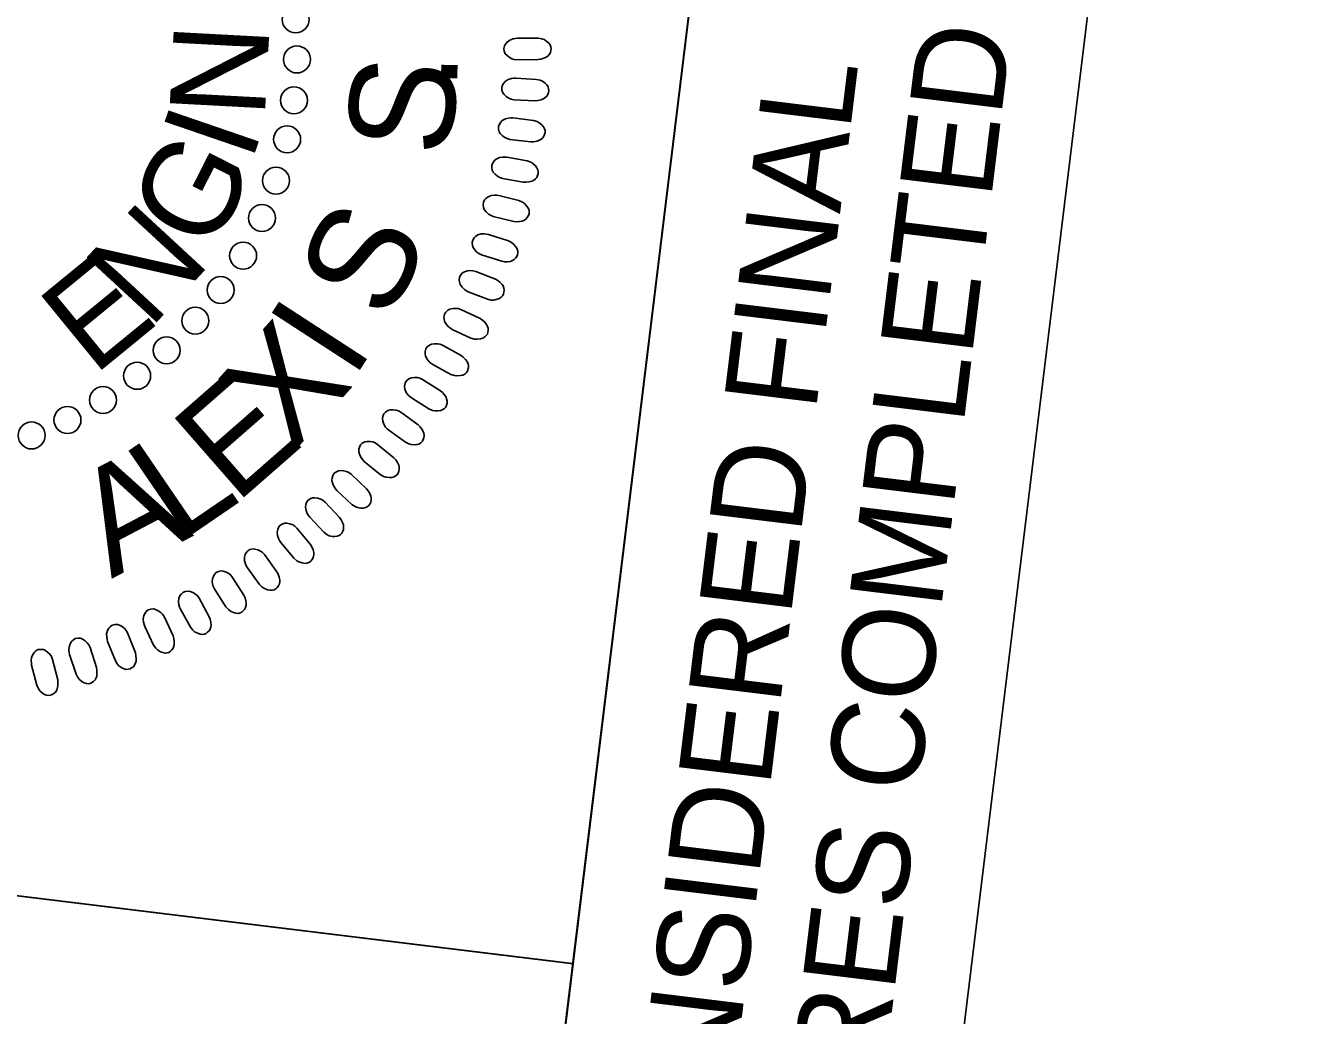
# Model space of a CAD drawing. Extents: x 480792 to 482083, y 490046 to 491850.
# Drawn here: x 481120.5 to 481196.3, y 491710 to 491768.8 of the extents above; entities that cross this region are included whole.
import ezdxf

# ---------------------------------------------------------------- set-up
doc = ezdxf.new("R2010")
doc.units = 0
for name, color, linetype in [('Sheet PE Seal Cell', 7, 'Continuous'), ('Sheet Plan CELL', 7, 'Continuous'), ('Sheet Sticker Exception Certification CELL', 7, 'Continuous')]:
    doc.layers.add(name, color=color, linetype=linetype)

msp = doc.modelspace()

# ---------------------------------------------------------------- linework, layer by layer
at = {"layer": 'Sheet PE Seal Cell'}
for points in [[(481149.711, 491768.037), (481150.937, 491768.041), (481151.157, 491768.005), (481151.297, 491767.954), (481151.467, 491767.842), (481151.577, 491767.745), (481151.657, 491767.633), (481151.697, 491767.529), (481151.718, 491767.416), (481151.698, 491767.305), (481151.669, 491767.185), (481151.61, 491767.08), (481151.51, 491766.975), (481151.43, 491766.915), (481151.281, 491766.847), (481151.102, 491766.786), (481150.942, 491766.763), (481149.686, 491766.751), (481149.516, 491766.773), (481149.376, 491766.818), (481149.217, 491766.907), (481149.077, 491767.017), (481148.996, 491767.115), (481148.936, 491767.271), (481148.915, 491767.422), (481148.955, 491767.571), (481149.005, 491767.676), (481149.103, 491767.803), (481149.272, 491767.923), (481149.452, 491767.991), (481149.581, 491768.021)], [(481149.616, 491765.665), (481150.841, 491765.592), (481151.058, 491765.543), (481151.194, 491765.483), (481151.357, 491765.36), (481151.461, 491765.257), (481151.533, 491765.14), (481151.567, 491765.034), (481151.58, 491764.92), (481151.553, 491764.81), (481151.517, 491764.692), (481151.451, 491764.591), (481151.345, 491764.492), (481151.262, 491764.437), (481151.109, 491764.379), (481150.926, 491764.33), (481150.765, 491764.317), (481149.51, 491764.383), (481149.342, 491764.416), (481149.206, 491764.469), (481149.052, 491764.569), (481148.919, 491764.688), (481148.845, 491764.79), (481148.795, 491764.95), (481148.784, 491765.101), (481148.832, 491765.247), (481148.888, 491765.349), (481148.995, 491765.47), (481149.172, 491765.579), (481149.355, 491765.636), (481149.486, 491765.658)], [(481149.451, 491763.301), (481150.669, 491763.151), (481150.881, 491763.088), (481151.014, 491763.019), (481151.169, 491762.887), (481151.266, 491762.777), (481151.331, 491762.656), (481151.358, 491762.548), (481151.364, 491762.434), (481151.331, 491762.325), (481151.287, 491762.21), (481151.215, 491762.113), (481151.103, 491762.021), (481151.016, 491761.972), (481150.859, 491761.923), (481150.674, 491761.886), (481150.513, 491761.883), (481149.265, 491762.028), (481149.1, 491762.071), (481148.966, 491762.133), (481148.819, 491762.241), (481148.694, 491762.369), (481148.626, 491762.476), (481148.586, 491762.639), (481148.585, 491762.79), (481148.642, 491762.933), (481148.705, 491763.031), (481148.818, 491763.145), (481149.001, 491763.243), (481149.188, 491763.288), (481149.32, 491763.301)], [(481149.094, 491760.974), (481150.3, 491760.748), (481150.509, 491760.671), (481150.637, 491760.594), (481150.783, 491760.453), (481150.873, 491760.337), (481150.93, 491760.213), (481150.951, 491760.102), (481150.949, 491759.988), (481150.909, 491759.882), (481150.858, 491759.77), (481150.78, 491759.678), (481150.663, 491759.594), (481150.573, 491759.549), (481150.414, 491759.51), (481150.226, 491759.484), (481150.065, 491759.492), (481148.829, 491759.715), (481148.666, 491759.768), (481148.537, 491759.838), (481148.397, 491759.956), (481148.28, 491760.091), (481148.22, 491760.202), (481148.19, 491760.367), (481148.198, 491760.518), (481148.265, 491760.658), (481148.333, 491760.751), (481148.454, 491760.858), (481148.643, 491760.944), (481148.832, 491760.977), (481148.964, 491760.982)], [(481148.617, 491758.697), (481149.807, 491758.397), (481150.01, 491758.307), (481150.133, 491758.222), (481150.27, 491758.072), (481150.352, 491757.95), (481150.403, 491757.822), (481150.415, 491757.711), (481150.407, 491757.597), (481150.36, 491757.494), (481150.302, 491757.385), (481150.219, 491757.298), (481150.096, 491757.222), (481150.004, 491757.183), (481149.842, 491757.154), (481149.654, 491757.14), (481149.494, 491757.157), (481148.274, 491757.458), (481148.115, 491757.521), (481147.99, 491757.6), (481147.858, 491757.725), (481147.749, 491757.868), (481147.696, 491757.982), (481147.676, 491758.149), (481147.694, 491758.299), (481147.769, 491758.434), (481147.843, 491758.523), (481147.971, 491758.622), (481148.164, 491758.695), (481148.355, 491758.717), (481148.488, 491758.714)], [(481148.007, 491756.388), (481149.175, 491756.013), (481149.372, 491755.911), (481149.49, 491755.819), (481149.617, 491755.66), (481149.691, 491755.534), (481149.733, 491755.403), (481149.739, 491755.291), (481149.723, 491755.178), (481149.671, 491755.078), (481149.606, 491754.973), (481149.517, 491754.891), (481149.39, 491754.822), (481149.296, 491754.789), (481149.133, 491754.771), (481148.943, 491754.769), (481148.784, 491754.796), (481147.586, 491755.173), (481147.431, 491755.246), (481147.312, 491755.332), (481147.187, 491755.466), (481147.089, 491755.615), (481147.042, 491755.732), (481147.033, 491755.899), (481147.06, 491756.049), (481147.144, 491756.178), (481147.223, 491756.263), (481147.356, 491756.354), (481147.554, 491756.415), (481147.746, 491756.425), (481147.878, 491756.413)], [(481146.798, 491752.988), (481147.94, 491752.54), (481148.157, 491752.496), (481148.307, 491752.493), (481148.506, 491752.536), (481148.644, 491752.586), (481148.758, 491752.662), (481148.834, 491752.744), (481148.893, 491752.841), (481148.915, 491752.953), (481148.931, 491753.076), (481148.914, 491753.194), (481148.859, 491753.328), (481148.807, 491753.413), (481148.692, 491753.53), (481148.546, 491753.651), (481148.406, 491753.73), (481147.239, 491754.196), (481147.073, 491754.236), (481146.926, 491754.245), (481146.745, 491754.22), (481146.574, 491754.167), (481146.464, 491754.105), (481146.351, 491753.981), (481146.279, 491753.849), (481146.261, 491753.695), (481146.27, 491753.58), (481146.316, 491753.425), (481146.43, 491753.252), (481146.573, 491753.123), (481146.683, 491753.049)], [(481145.847, 491750.754), (481146.959, 491750.236), (481147.174, 491750.177), (481147.322, 491750.165), (481147.523, 491750.195), (481147.664, 491750.237), (481147.784, 491750.305), (481147.863, 491750.383), (481147.929, 491750.476), (481147.958, 491750.586), (481147.982, 491750.707), (481147.972, 491750.827), (481147.925, 491750.964), (481147.878, 491751.052), (481147.771, 491751.177), (481147.634, 491751.306), (481147.499, 491751.394), (481146.363, 491751.932), (481146.199, 491751.983), (481146.054, 491752.001), (481145.872, 491751.987), (481145.698, 491751.945), (481145.584, 491751.89), (481145.464, 491751.773), (481145.383, 491751.646), (481145.356, 491751.494), (481145.357, 491751.378), (481145.393, 491751.22), (481145.496, 491751.041), (481145.631, 491750.904), (481145.736, 491750.822)], [(481144.684, 491748.671), (481145.761, 491748.084), (481145.972, 491748.011), (481146.119, 491747.99), (481146.322, 491748.008), (481146.465, 491748.04), (481146.588, 491748.101), (481146.673, 491748.174), (481146.745, 491748.263), (481146.78, 491748.37), (481146.812, 491748.49), (481146.81, 491748.61), (481146.771, 491748.75), (481146.73, 491748.841), (481146.631, 491748.971), (481146.502, 491749.11), (481146.373, 491749.206), (481145.273, 491749.814), (481145.113, 491749.875), (481144.969, 491749.902), (481144.786, 491749.9), (481144.61, 491749.869), (481144.493, 491749.821), (481144.365, 491749.712), (481144.276, 491749.59), (481144.24, 491749.44), (481144.234, 491749.324), (481144.26, 491749.165), (481144.352, 491748.979), (481144.478, 491748.834), (481144.577, 491748.746)], [(481143.425, 491746.681), (481144.463, 491746.028), (481144.669, 491745.943), (481144.815, 491745.912), (481145.018, 491745.917), (481145.163, 491745.941), (481145.29, 491745.993), (481145.379, 491746.06), (481145.456, 491746.145), (481145.498, 491746.25), (481145.537, 491746.367), (481145.542, 491746.488), (481145.513, 491746.63), (481145.478, 491746.723), (481145.387, 491746.859), (481145.267, 491747.006), (481145.144, 491747.11), (481144.085, 491747.785), (481143.929, 491747.857), (481143.787, 491747.892), (481143.604, 491747.902), (481143.426, 491747.882), (481143.307, 491747.841), (481143.173, 491747.74), (481143.076, 491747.624), (481143.03, 491747.477), (481143.017, 491747.361), (481143.033, 491747.201), (481143.113, 491747.01), (481143.23, 491746.857), (481143.323, 491746.763)], [(481142.077, 491744.771), (481143.072, 491744.054), (481143.272, 491743.956), (481143.416, 491743.916), (481143.619, 491743.908), (481143.765, 491743.923), (481143.895, 491743.967), (481143.989, 491744.028), (481144.071, 491744.109), (481144.119, 491744.21), (481144.165, 491744.325), (481144.179, 491744.445), (481144.158, 491744.588), (481144.129, 491744.683), (481144.047, 491744.826), (481143.936, 491744.979), (481143.82, 491745.091), (481142.804, 491745.831), (481142.654, 491745.912), (481142.514, 491745.957), (481142.332, 491745.978), (481142.154, 491745.969), (481142.032, 491745.937), (481141.892, 491745.844), (481141.788, 491745.734), (481141.733, 491745.59), (481141.712, 491745.476), (481141.719, 491745.314), (481141.787, 491745.119), (481141.893, 491744.958), (481141.98, 491744.859)], [(481140.626, 491742.915), (481141.575, 491742.137), (481141.767, 491742.026), (481141.908, 491741.978), (481142.111, 491741.957), (481142.257, 491741.963), (481142.39, 491741.999), (481142.487, 491742.054), (481142.573, 491742.129), (481142.629, 491742.228), (481142.683, 491742.339), (481142.702, 491742.458), (481142.692, 491742.602), (481142.668, 491742.699), (481142.595, 491742.846), (481142.494, 491743.006), (481142.385, 491743.125), (481141.419, 491743.928), (481141.273, 491744.018), (481141.137, 491744.071), (481140.957, 491744.104), (481140.778, 491744.106), (481140.654, 491744.081), (481140.508, 491743.998), (481140.398, 491743.895), (481140.334, 491743.754), (481140.306, 491743.641), (481140.302, 491743.48), (481140.358, 491743.28), (481140.454, 491743.114), (481140.535, 491743.009)], [(481138.992, 491741.199), (481139.89, 491740.363), (481140.076, 491740.241), (481140.214, 491740.183), (481140.415, 491740.149), (481140.561, 491740.146), (481140.696, 491740.174), (481140.796, 491740.223), (481140.888, 491740.292), (481140.949, 491740.387), (481141.009, 491740.495), (481141.037, 491740.612), (481141.035, 491740.757), (481141.018, 491740.855), (481140.953, 491741.006), (481140.863, 491741.172), (481140.762, 491741.298), (481139.848, 491742.159), (481139.708, 491742.259), (481139.575, 491742.321), (481139.398, 491742.364), (481139.219, 491742.378), (481139.095, 491742.361), (481138.943, 491742.287), (481138.827, 491742.191), (481138.754, 491742.054), (481138.72, 491741.944), (481138.705, 491741.783), (481138.749, 491741.58), (481138.834, 491741.408), (481138.908, 491741.298)], [(481137.386, 491739.601), (481138.23, 491738.709), (481138.408, 491738.576), (481138.541, 491738.51), (481138.739, 491738.464), (481138.886, 491738.452), (481139.022, 491738.471), (481139.126, 491738.513), (481139.221, 491738.576), (481139.288, 491738.667), (481139.354, 491738.772), (481139.389, 491738.886), (481139.396, 491739.032), (481139.386, 491739.131), (481139.332, 491739.285), (481139.252, 491739.457), (481139.158, 491739.588), (481138.3, 491740.506), (481138.167, 491740.614), (481138.038, 491740.684), (481137.864, 491740.738), (481137.687, 491740.763), (481137.56, 491740.754), (481137.406, 491740.69), (481137.283, 491740.601), (481137.202, 491740.47), (481137.161, 491740.361), (481137.137, 491740.202), (481137.167, 491739.997), (481137.241, 491739.819), (481137.308, 491739.705)], [(481135.663, 491738.109), (481136.448, 491737.167), (481136.617, 491737.022), (481136.747, 491736.948), (481136.942, 491736.89), (481137.087, 491736.867), (481137.224, 491736.878), (481137.329, 491736.915), (481137.429, 491736.971), (481137.501, 491737.058), (481137.574, 491737.158), (481137.617, 491737.271), (481137.633, 491737.414), (481137.628, 491737.514), (481137.584, 491737.672), (481137.515, 491737.848), (481137.43, 491737.985), (481136.631, 491738.955), (481136.505, 491739.071), (481136.381, 491739.149), (481136.21, 491739.215), (481136.035, 491739.25), (481135.909, 491739.249), (481135.75, 491739.195), (481135.622, 491739.114), (481135.533, 491738.987), (481135.485, 491738.882), (481135.451, 491738.724), (481135.468, 491738.518), (481135.531, 491738.336), (481135.591, 491738.218)], [(481133.687, 491736.602), (481134.412, 491735.612), (481134.571, 491735.457), (481134.696, 491735.375), (481134.887, 491735.305), (481135.03, 491735.274), (481135.168, 491735.276), (481135.276, 491735.305), (481135.378, 491735.356), (481135.457, 491735.438), (481135.536, 491735.533), (481135.584, 491735.642), (481135.61, 491735.785), (481135.611, 491735.884), (481135.577, 491736.046), (481135.519, 491736.226), (481135.443, 491736.367), (481134.707, 491737.385), (481134.588, 491737.509), (481134.469, 491737.595), (481134.303, 491737.671), (481134.13, 491737.718), (481134.005, 491737.724), (481133.842, 491737.68), (481133.71, 491737.607), (481133.613, 491737.487), (481133.558, 491737.385), (481133.514, 491737.229), (481133.518, 491737.022), (481133.57, 491736.837), (481133.623, 491736.715)], [(481131.747, 491735.318), (481132.408, 491734.284), (481132.557, 491734.12), (481132.677, 491734.03), (481132.863, 491733.948), (481133.003, 491733.908), (481133.141, 491733.901), (481133.25, 491733.924), (481133.356, 491733.968), (481133.439, 491734.045), (481133.524, 491734.135), (481133.58, 491734.241), (481133.614, 491734.381), (481133.622, 491734.481), (481133.598, 491734.644), (481133.551, 491734.827), (481133.485, 491734.973), (481132.813, 491736.036), (481132.703, 491736.166), (481132.589, 491736.26), (481132.428, 491736.346), (481132.259, 491736.403), (481132.134, 491736.418), (481131.969, 491736.384), (481131.833, 491736.32), (481131.729, 491736.206), (481131.667, 491736.107), (481131.613, 491735.954), (481131.604, 491735.748), (481131.644, 491735.56), (481131.689, 491735.435)], [(481129.709, 491734.153), (481130.304, 491733.079), (481130.443, 491732.906), (481130.556, 491732.808), (481130.737, 491732.715), (481130.875, 491732.667), (481131.012, 491732.651), (481131.122, 491732.667), (481131.231, 491732.704), (481131.319, 491732.776), (481131.409, 491732.86), (481131.472, 491732.963), (481131.514, 491733.101), (481131.528, 491733.2), (481131.514, 491733.363), (481131.48, 491733.549), (481131.422, 491733.7), (481130.819, 491734.802), (481130.717, 491734.94), (481130.61, 491735.04), (481130.454, 491735.136), (481130.289, 491735.203), (481130.165, 491735.226), (481129.998, 491735.203), (481129.858, 491735.147), (481129.747, 491735.04), (481129.679, 491734.945), (481129.616, 491734.797), (481129.594, 491734.591), (481129.622, 491734.401), (481129.659, 491734.273)], [(481127.594, 491733.125), (481128.121, 491732.017), (481128.248, 491731.834), (481128.355, 491731.731), (481128.53, 491731.626), (481128.664, 491731.569), (481128.8, 491731.545), (481128.911, 491731.554), (481129.021, 491731.584), (481129.114, 491731.65), (481129.209, 491731.728), (481129.278, 491731.827), (481129.33, 491731.962), (481129.349, 491732.06), (481129.346, 491732.224), (481129.323, 491732.412), (481129.275, 491732.565), (481128.742, 491733.704), (481128.649, 491733.847), (481128.548, 491733.954), (481128.399, 491734.059), (481128.238, 491734.138), (481128.116, 491734.168), (481127.948, 491734.154), (481127.805, 491734.108), (481127.687, 491734.008), (481127.614, 491733.918), (481127.542, 491733.773), (481127.507, 491733.569), (481127.523, 491733.377), (481127.552, 491733.248)], [(481125.394, 491732.229), (481125.85, 491731.089), (481125.966, 491730.9), (481126.067, 491730.79), (481126.233, 491730.674), (481126.365, 491730.608), (481126.498, 491730.576), (481126.61, 491730.578), (481126.722, 491730.601), (481126.818, 491730.661), (481126.918, 491730.734), (481126.993, 491730.828), (481127.053, 491730.96), (481127.08, 491731.056), (481127.086, 491731.219), (481127.075, 491731.408), (481127.037, 491731.565), (481126.577, 491732.734), (481126.492, 491732.884), (481126.399, 491732.996), (481126.256, 491733.111), (481126.101, 491733.199), (481125.981, 491733.237), (481125.813, 491733.234), (481125.666, 491733.197), (481125.542, 491733.104), (481125.464, 491733.019), (481125.383, 491732.88), (481125.335, 491732.677), (481125.339, 491732.485), (481125.36, 491732.354)], [(481123.134, 491731.45), (481123.518, 491730.284), (481123.622, 491730.088), (481123.715, 491729.971), (481123.875, 491729.845), (481124.002, 491729.771), (481124.133, 491729.731), (481124.245, 491729.726), (481124.358, 491729.741), (481124.457, 491729.796), (481124.562, 491729.862), (481124.643, 491729.951), (481124.711, 491730.079), (481124.743, 491730.173), (481124.76, 491730.336), (481124.76, 491730.526), (481124.732, 491730.684), (481124.346, 491731.88), (481124.272, 491732.034), (481124.186, 491732.152), (481124.051, 491732.276), (481123.901, 491732.374), (481123.783, 491732.419), (481123.615, 491732.427), (481123.467, 491732.399), (481123.338, 491732.314), (481123.254, 491732.234), (481123.164, 491732.1), (481123.104, 491731.902), (481123.096, 491731.71), (481123.108, 491731.577)], [(481120.882, 491730.819), (481121.191, 491729.631), (481121.283, 491729.428), (481121.368, 491729.306), (481121.52, 491729.17), (481121.642, 491729.089), (481121.771, 491729.04), (481121.881, 491729.028), (481121.995, 491729.037), (481122.098, 491729.084), (481122.207, 491729.144), (481122.293, 491729.227), (481122.369, 491729.351), (481122.407, 491729.443), (481122.434, 491729.605), (481122.446, 491729.793), (481122.428, 491729.954), (481122.118, 491731.171), (481122.054, 491731.33), (481121.975, 491731.454), (481121.848, 491731.585), (481121.704, 491731.692), (481121.59, 491731.745), (481121.423, 491731.763), (481121.273, 491731.745), (481121.139, 491731.669), (481121.05, 491731.594), (481120.952, 491731.465), (481120.88, 491731.271), (481120.859, 491731.08), (481120.864, 491730.947)]]:
    msp.add_lwpolyline(points, close=True, dxfattribs=at)
for centre in [(481136.556, 491769.147), (481136.626, 491766.772), (481136.45, 491764.347), (481136.045, 491762.03), (481135.385, 491759.584), (481134.55, 491757.359), (481133.434, 491755.129), (481132.101, 491753.087), (481130.593, 491751.266), (481128.893, 491749.509), (481127.143, 491747.998), (481125.121, 491746.561), (481123.009, 491745.376), (481120.878, 491744.458)]:
    msp.add_circle(centre, 0.801, dxfattribs=at)
at = {"layer": 'Sheet Plan CELL'}
msp.add_line((481041.344, 491726.742), (481152.979, 491713.12), dxfattribs=at)
for points in [[(481041.344, 491726.742), (481053.454, 491825.994), (481165.138, 491812.366), (481153.027, 491713.102)], [(481876.581, 490214.312), (480834.348, 490341.583), (480991.917, 491631.986), (481140.874, 491613.805), (481165.138, 491812.366), (482058.438, 491703.26)], [(481029.215, 491627.43), (481041.344, 491726.742), (481153.027, 491713.102), (481140.874, 491613.805)]]:
    msp.add_lwpolyline(points, close=True, dxfattribs=at)
at = {"layer": 'Sheet Sticker Exception Certification CELL'}
for p, q in [((481140.874, 491613.805), (481165.126, 491812.367)), ((481140.874, 491613.805), (481165.126, 491812.367)), ((481188.453, 491809.518), (481164.201, 491610.956)), ((481188.453, 491809.518), (481164.201, 491610.956))]:
    msp.add_line(p, q, dxfattribs=at)

# ---------------------------------------------------------------- texts
at = {"layer": 'Sheet PE Seal Cell'}
for s, height, rotation, p in [('N', 5.669, 86.94089, (481134.713, 491763.253)), ('S', 6.236, 82.41913, (481145.603, 491760.883)), ('.', 6.236, 89.26478, (481146.141, 491764.887)), ('I', 5.669, 71.06129, (481133.91, 491760.577)), ('G', 5.669, 63.12149, (481131.551, 491755.195)), ('N', 5.669, 47.2419, (481127.882, 491750.713)), ('S', 6.236, 63.82393, (481142.07, 491751.118)), ('E', 5.669, 39.3021, (481124.568, 491747.959)), ('I', 6.236, 56.97827, (481139.946, 491747.695)), ('X', 6.236, 48.03095, (481136.332, 491743.352)), ('E', 6.236, 41.18529, (481132.969, 491740.336)), ('L', 6.236, 34.33964, (481129.581, 491738.017)), ('A', 6.236, 27.71996, (481125.62, 491735.941))]:
    msp.add_text(s, height=height, rotation=rotation, dxfattribs=at).set_placement(p)
at = {"layer": 'Sheet Sticker Exception Certification CELL'}
for s, p in [('UNLESS ALL SIGNATURES COMPLETED', (481161.818, 491627.366)), ('UNLESS ALL SIGNATURES COMPLETED', (481161.818, 491627.366)), ('DOCUMENT NOT CONSIDERED FINAL', (481153.698, 491633.466)), ('DOCUMENT NOT CONSIDERED FINAL', (481153.698, 491633.466))]:
    msp.add_text(s, height=5.5, rotation=83.03651, dxfattribs=at).set_placement(p)

doc.saveas('drawing.dxf')
